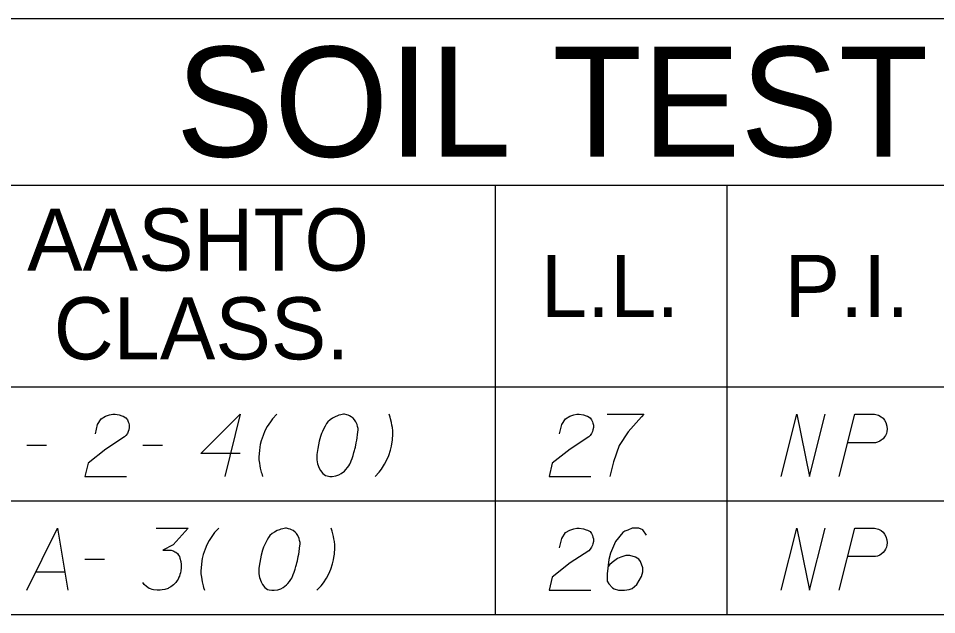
# Model space of a CAD drawing. Extents: x 2074207 to 2076812, y 516372 to 523312.
# Drawn here: x 2076453.5 to 2076524.4, y 516372.3 to 516418.4 of the extents above; entities that cross this region are included whole.
import ezdxf

# ---------------------------------------------------------------- set-up
doc = ezdxf.new("R2010")
doc.units = 0
for name, color, linetype in [('Prop DirtTable_ Soil Test Results - Outline (Major)', 7, 'Continuous'), ('Prop DirtTable_ Soil Test Results - Outline (Minor)', 7, 'Continuous'), ('Prop DirtTable_ Soil Test Results - Tx (Header - Large)', 7, 'Continuous'), ('Prop DirtTable_ Soil Test Results - Tx (Header - Small)', 7, 'Continuous'), ('Prop DirtTable_ Soil Test Results - Tx (Sample Data)', 7, 'Continuous')]:
    doc.layers.add(name, color=color, linetype=linetype)

msp = doc.modelspace()

# ---------------------------------------------------------------- linework, layer by layer
at = {"layer": 'Prop DirtTable_ Soil Test Results - Outline (Major)'}
for p, q in [((2076260.609, 516418.371), (2076811.903, 516418.371)), ((2076260.609, 516389.885), (2076811.903, 516389.885)), ((2076260.609, 516389.885), (2076811.903, 516389.885)), ((2076260.609, 516372.285), (2076811.903, 516372.285))]:
    msp.add_line(p, q, dxfattribs=at)
at = {"layer": 'Prop DirtTable_ Soil Test Results - Outline (Minor)'}
for p, q in [((2076260.609, 516405.485), (2076811.903, 516405.485)), ((2076490.31, 516405.485), (2076490.31, 516381.085)), ((2076508.192, 516405.485), (2076508.192, 516381.085)), ((2076260.609, 516381.085), (2076811.903, 516381.085)), ((2076260.609, 516381.085), (2076811.903, 516381.085)), ((2076490.31, 516381.085), (2076490.31, 516372.285)), ((2076508.192, 516381.085), (2076508.192, 516372.285)), ((2076260.609, 516372.285), (2076811.903, 516372.285))]:
    msp.add_line(p, q, dxfattribs=at)
at = {"layer": 'Prop DirtTable_ Soil Test Results - Tx (Sample Data)'}
for points in [[(2076459.447, 516386.255), (2076459.623, 516386.973), (2076459.906, 516387.426), (2076460.223, 516387.615), (2076460.54, 516387.729), (2076460.787, 516387.767), (2076460.964, 516387.767), (2076461.281, 516387.729), (2076461.493, 516387.653), (2076461.599, 516387.615), (2076461.81, 516387.502), (2076461.916, 516387.351), (2076461.987, 516387.2), (2076462.022, 516387.086), (2076462.057, 516386.935), (2076462.057, 516386.746), (2076462.022, 516386.557), (2076461.987, 516386.444), (2076461.916, 516386.293), (2076461.81, 516386.141), (2076461.705, 516386.028), (2076460.258, 516385.083), (2076458.883, 516383.987), (2076458.636, 516382.967), (2076461.846, 516382.967)], [(2076470.629, 516384.743), (2076467.596, 516384.743), (2076470.629, 516387.767), (2076469.43, 516382.967)], [(2076473.451, 516387.767), (2076473.134, 516387.426), (2076472.958, 516387.2), (2076472.711, 516386.822), (2076472.534, 516386.482), (2076472.393, 516386.141), (2076472.252, 516385.726), (2076472.181, 516385.423), (2076472.146, 516385.234), (2076472.111, 516384.97), (2076472.076, 516384.478), (2076472.076, 516384.252), (2076472.111, 516383.987), (2076472.146, 516383.798), (2076472.181, 516383.609), (2076472.252, 516383.307), (2076472.287, 516383.193), (2076472.358, 516382.967)], [(2076478.672, 516387.767), (2076478.602, 516387.767), (2076478.39, 516387.729), (2076478.249, 516387.691), (2076478.143, 516387.653), (2076477.967, 516387.578), (2076477.755, 516387.464), (2076477.579, 516387.351), (2076477.402, 516387.2), (2076477.296, 516387.049), (2076477.191, 516386.86), (2076477.085, 516386.671), (2076476.979, 516386.444), (2076476.908, 516386.293), (2076476.838, 516386.066), (2076476.732, 516385.688), (2076476.626, 516385.121), (2076476.556, 516384.667), (2076476.556, 516384.252), (2076476.591, 516383.949), (2076476.732, 516383.609), (2076476.838, 516383.42), (2076477.014, 516383.193), (2076477.226, 516383.042), (2076477.332, 516383.004), (2076477.543, 516382.967), (2076477.72, 516382.967), (2076478.002, 516383.004), (2076478.249, 516383.08), (2076478.425, 516383.193), (2076478.672, 516383.382), (2076478.778, 516383.496), (2076478.919, 516383.647), (2076479.025, 516383.798), (2076479.095, 516383.912), (2076479.166, 516384.1), (2076479.201, 516384.176), (2076479.272, 516384.365), (2076479.342, 516384.592), (2076479.413, 516384.819), (2076479.448, 516384.97), (2076479.483, 516385.083), (2076479.519, 516385.234), (2076479.589, 516385.575), (2076479.625, 516385.763), (2076479.66, 516385.952), (2076479.695, 516386.217), (2076479.73, 516386.557), (2076479.73, 516386.671), (2076479.695, 516386.822), (2076479.66, 516386.973), (2076479.554, 516387.2), (2076479.448, 516387.351), (2076479.342, 516387.464), (2076479.201, 516387.578), (2076479.06, 516387.653), (2076478.954, 516387.691), (2076478.849, 516387.729), (2076478.672, 516387.767)], [(2076481.036, 516382.967), (2076481.353, 516383.307), (2076481.529, 516383.534), (2076481.776, 516383.912), (2076481.953, 516384.252), (2076482.094, 516384.592), (2076482.235, 516385.008), (2076482.306, 516385.31), (2076482.341, 516385.499), (2076482.376, 516385.763), (2076482.411, 516386.255), (2076482.411, 516386.482), (2076482.376, 516386.746), (2076482.341, 516386.935), (2076482.306, 516387.124), (2076482.235, 516387.426), (2076482.2, 516387.54), (2076482.129, 516387.767)], [(2076495.287, 516386.255), (2076495.463, 516386.973), (2076495.746, 516387.426), (2076496.063, 516387.615), (2076496.38, 516387.729), (2076496.627, 516387.767), (2076496.804, 516387.767), (2076497.121, 516387.729), (2076497.333, 516387.653), (2076497.439, 516387.615), (2076497.65, 516387.502), (2076497.756, 516387.351), (2076497.827, 516387.2), (2076497.862, 516387.086), (2076497.897, 516386.935), (2076497.897, 516386.746), (2076497.862, 516386.557), (2076497.827, 516386.444), (2076497.756, 516386.293), (2076497.65, 516386.141), (2076497.545, 516386.028), (2076496.098, 516385.083), (2076494.723, 516383.987), (2076494.476, 516382.967), (2076497.686, 516382.967)], [(2076498.956, 516387.767), (2076501.778, 516387.767), (2076501.601, 516387.578), (2076500.578, 516386.406), (2076499.873, 516385.348), (2076499.449, 516384.1), (2076499.167, 516382.967)], [(2076512.396, 516382.967), (2076513.595, 516387.767), (2076514.583, 516382.967), (2076515.782, 516387.767)], [(2076516.876, 516382.967), (2076518.075, 516387.767), (2076519.592, 516387.767), (2076519.803, 516387.729), (2076519.909, 516387.691), (2076520.121, 516387.578), (2076520.262, 516387.464), (2076520.368, 516387.313), (2076520.474, 516387.124), (2076520.544, 516386.86), (2076520.58, 516386.633), (2076520.544, 516386.444), (2076520.509, 516386.293), (2076520.438, 516386.141), (2076520.368, 516386.028), (2076520.262, 516385.877), (2076520.121, 516385.763), (2076520.015, 516385.688), (2076519.839, 516385.612), (2076519.662, 516385.575), (2076517.546, 516385.575)], [(2076454.156, 516385.386), (2076455.672, 516385.386)], [(2076463.116, 516385.386), (2076464.632, 516385.386)], [(2076454.156, 516374.167), (2076456.519, 516378.967), (2076457.33, 516374.167)], [(2076464.139, 516378.967), (2076466.608, 516378.967), (2076465.444, 516377.682), (2076464.668, 516377.266), (2076465.303, 516377.266), (2076465.444, 516377.228), (2076465.514, 516377.19), (2076465.585, 516377.152), (2076465.655, 516377.115), (2076465.797, 516377.001), (2076465.867, 516376.888), (2076465.938, 516376.775), (2076465.973, 516376.661), (2076466.043, 516376.397), (2076466.079, 516376.17), (2076466.079, 516376.056), (2076466.079, 516375.905), (2076466.043, 516375.678), (2076466.008, 516375.527), (2076465.973, 516375.376), (2076465.938, 516375.263), (2076465.902, 516375.187), (2076465.867, 516375.112), (2076465.832, 516375.036), (2076465.761, 516374.923), (2076465.655, 516374.771), (2076465.55, 516374.658), (2076465.479, 516374.582), (2076465.373, 516374.507), (2076465.267, 516374.431), (2076465.126, 516374.356), (2076465.056, 516374.318), (2076464.809, 516374.242), (2076464.597, 516374.204), (2076464.456, 516374.167), (2076464.209, 516374.167), (2076463.927, 516374.204), (2076463.821, 516374.242), (2076463.715, 516374.28), (2076463.609, 516374.318), (2076463.504, 516374.393), (2076463.398, 516374.469), (2076463.221, 516374.62), (2076463.116, 516374.771)], [(2076468.971, 516378.967), (2076468.654, 516378.626), (2076468.478, 516378.4), (2076468.231, 516378.022), (2076468.054, 516377.682), (2076467.913, 516377.341), (2076467.772, 516376.926), (2076467.701, 516376.623), (2076467.666, 516376.434), (2076467.631, 516376.17), (2076467.596, 516375.678), (2076467.596, 516375.452), (2076467.631, 516375.187), (2076467.666, 516374.998), (2076467.701, 516374.809), (2076467.772, 516374.507), (2076467.807, 516374.393), (2076467.878, 516374.167)], [(2076474.192, 516378.967), (2076474.122, 516378.967), (2076473.91, 516378.929), (2076473.769, 516378.891), (2076473.663, 516378.853), (2076473.487, 516378.778), (2076473.275, 516378.664), (2076473.099, 516378.551), (2076472.922, 516378.4), (2076472.816, 516378.249), (2076472.711, 516378.06), (2076472.605, 516377.871), (2076472.499, 516377.644), (2076472.428, 516377.493), (2076472.358, 516377.266), (2076472.252, 516376.888), (2076472.146, 516376.321), (2076472.076, 516375.867), (2076472.076, 516375.452), (2076472.111, 516375.149), (2076472.252, 516374.809), (2076472.358, 516374.62), (2076472.534, 516374.393), (2076472.746, 516374.242), (2076472.852, 516374.204), (2076473.063, 516374.167), (2076473.24, 516374.167), (2076473.522, 516374.204), (2076473.769, 516374.28), (2076473.945, 516374.393), (2076474.192, 516374.582), (2076474.298, 516374.696), (2076474.439, 516374.847), (2076474.545, 516374.998), (2076474.615, 516375.112), (2076474.686, 516375.3), (2076474.721, 516375.376), (2076474.792, 516375.565), (2076474.862, 516375.792), (2076474.933, 516376.019), (2076474.968, 516376.17), (2076475.003, 516376.283), (2076475.039, 516376.434), (2076475.109, 516376.775), (2076475.145, 516376.963), (2076475.18, 516377.152), (2076475.215, 516377.417), (2076475.25, 516377.757), (2076475.25, 516377.871), (2076475.215, 516378.022), (2076475.18, 516378.173), (2076475.074, 516378.4), (2076474.968, 516378.551), (2076474.862, 516378.664), (2076474.721, 516378.778), (2076474.58, 516378.853), (2076474.474, 516378.891), (2076474.369, 516378.929), (2076474.192, 516378.967)], [(2076476.556, 516374.167), (2076476.873, 516374.507), (2076477.049, 516374.734), (2076477.296, 516375.112), (2076477.473, 516375.452), (2076477.614, 516375.792), (2076477.755, 516376.208), (2076477.826, 516376.51), (2076477.861, 516376.699), (2076477.896, 516376.963), (2076477.931, 516377.455), (2076477.931, 516377.682), (2076477.896, 516377.946), (2076477.861, 516378.135), (2076477.826, 516378.324), (2076477.755, 516378.626), (2076477.72, 516378.74), (2076477.649, 516378.967)], [(2076495.287, 516377.455), (2076495.463, 516378.173), (2076495.746, 516378.626), (2076496.063, 516378.815), (2076496.38, 516378.929), (2076496.627, 516378.967), (2076496.804, 516378.967), (2076497.121, 516378.929), (2076497.333, 516378.853), (2076497.439, 516378.815), (2076497.65, 516378.702), (2076497.756, 516378.551), (2076497.827, 516378.4), (2076497.862, 516378.286), (2076497.897, 516378.135), (2076497.897, 516377.946), (2076497.862, 516377.757), (2076497.827, 516377.644), (2076497.756, 516377.493), (2076497.65, 516377.341), (2076497.545, 516377.228), (2076496.098, 516376.283), (2076494.723, 516375.187), (2076494.476, 516374.167), (2076497.686, 516374.167)], [(2076501.989, 516378.438), (2076501.707, 516378.853), (2076501.39, 516378.967), (2076500.896, 516378.967), (2076500.543, 516378.815), (2076500.331, 516378.74), (2076500.155, 516378.626), (2076499.591, 516377.946), (2076499.203, 516377.039), (2076499.097, 516376.548), (2076498.956, 516375.452), (2076498.956, 516374.885), (2076499.097, 516374.658), (2076499.379, 516374.356), (2076499.485, 516374.28), (2076499.838, 516374.167), (2076500.296, 516374.167), (2076500.649, 516374.242), (2076500.896, 516374.318), (2076501.249, 516374.62), (2076501.601, 516375.225), (2076501.707, 516375.603), (2076501.707, 516375.905), (2076501.531, 516376.397), (2076501.39, 516376.586), (2076501.143, 516376.737), (2076500.719, 516376.85), (2076500.402, 516376.85), (2076500.014, 516376.737), (2076499.767, 516376.623), (2076499.344, 516376.321), (2076499.132, 516376.132), (2076499.026, 516376.019)], [(2076512.396, 516374.167), (2076513.595, 516378.967), (2076514.583, 516374.167), (2076515.782, 516378.967)], [(2076516.876, 516374.167), (2076518.075, 516378.967), (2076519.592, 516378.967), (2076519.803, 516378.929), (2076519.909, 516378.891), (2076520.121, 516378.778), (2076520.262, 516378.664), (2076520.368, 516378.513), (2076520.474, 516378.324), (2076520.544, 516378.06), (2076520.58, 516377.833), (2076520.544, 516377.644), (2076520.509, 516377.493), (2076520.438, 516377.341), (2076520.368, 516377.228), (2076520.262, 516377.077), (2076520.121, 516376.963), (2076520.015, 516376.888), (2076519.839, 516376.812), (2076519.662, 516376.775), (2076517.546, 516376.775)], [(2076458.636, 516376.586), (2076460.152, 516376.586)], [(2076454.861, 516375.603), (2076457.083, 516375.603)]]:
    msp.add_lwpolyline(points, dxfattribs=at)

# ---------------------------------------------------------------- texts
at = {"layer": 'Prop DirtTable_ Soil Test Results - Tx (Header - Large)'}
msp.add_text('SOIL TEST RESULTS', height=8.50001, dxfattribs=at).set_placement((2076465.656, 516407.678))
at = {"layer": 'Prop DirtTable_ Soil Test Results - Tx (Header - Small)'}
for s, p in [('AASHTO', (2076454.182, 516398.872)), ('L.L.', (2076493.827, 516395.285)), ('P.I.', (2076512.654, 516395.285)), ('CLASS.', (2076456.225, 516392.014))]:
    msp.add_text(s, height=4.8, dxfattribs=at).set_placement(p)

doc.saveas('drawing.dxf')
